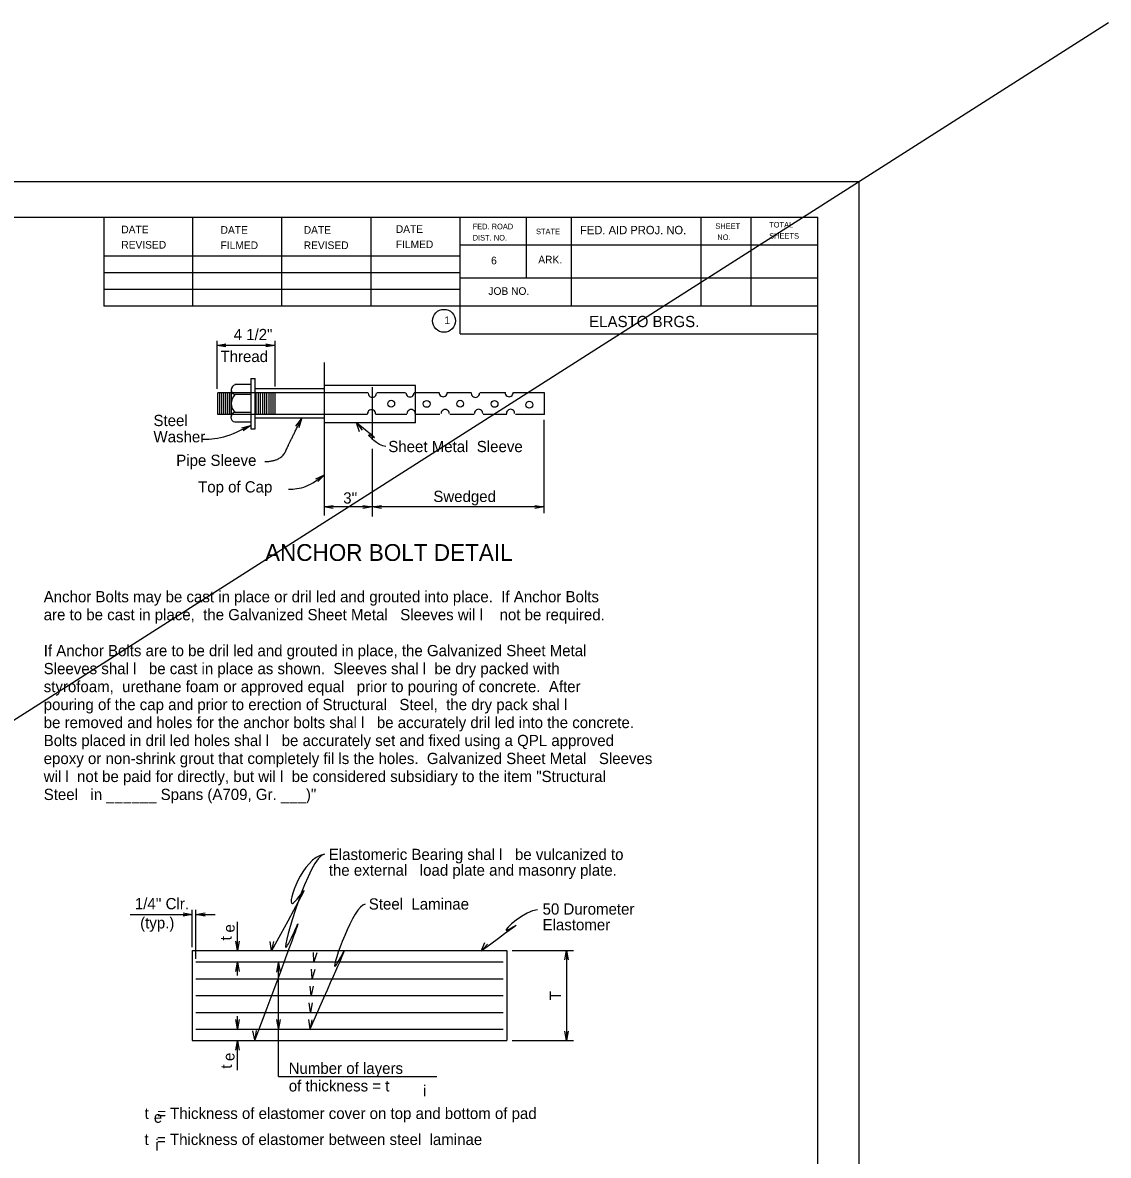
# Model space of a CAD drawing. Extents: x 113 to 232, y -103 to -27.
# Drawn here: x 192.72 to 200.77, y -74.97 to -66.57 of the extents above; entities that cross this region are included whole.
import ezdxf

# ---------------------------------------------------------------- set-up
doc = ezdxf.new("R2010")
doc.units = 0
for name, color, linetype in [('1', 7, 'Continuous'), ('B_Border', 7, 'Continuous'), ('B_Dimension', 7, 'Continuous'), ('B_No_Plot', 7, 'Continuous')]:
    doc.layers.add(name, color=color, linetype=linetype)

msp = doc.modelspace()

# ---------------------------------------------------------------- linework, layer by layer
at = {"layer": '1'}
for p, q in [((174.5006, -83.3011), (200.7719, -66.569)), ((194.1573, -68.9289), (194.1573, -69.2841)), ((194.589, -68.9629), (194.1573, -68.9629)), ((194.589, -68.9289), (194.589, -69.1692)), ((194.9551, -69.091), (194.9551, -70.224)), ((194.4108, -69.2081), (194.4108, -69.5831)), ((194.4108, -69.2081), (194.4421, -69.2081)), ((194.4421, -69.5831), (194.4421, -69.2081)), ((194.589, -69.1569), (194.589, -69.2681)), ((194.2581, -69.3147), (194.1646, -69.3147)), ((194.1646, -69.4745), (194.1646, -69.3147)), ((194.1796, -69.4745), (194.1796, -69.3147)), ((194.1946, -69.4745), (194.1946, -69.3147)), ((194.2096, -69.4745), (194.2096, -69.3147)), ((194.2246, -69.4745), (194.2246, -69.3147)), ((194.2396, -69.4745), (194.2396, -69.3147)), ((194.2553, -69.4745), (194.2553, -69.3147)), ((194.2637, -69.2843), (194.2637, -69.4899)), ((195.2811, -69.3147), (194.2637, -69.3147)), ((194.4108, -69.2524), (194.2912, -69.2524)), ((194.9551, -69.285), (194.4421, -69.285)), ((194.4506, -69.4745), (194.4506, -69.3147)), ((194.4664, -69.4745), (194.4664, -69.3147)), ((194.4822, -69.4745), (194.4822, -69.3147)), ((194.4981, -69.4745), (194.4981, -69.3147)), ((194.5138, -69.4745), (194.5138, -69.3147)), ((194.5296, -69.4745), (194.5296, -69.3147)), ((194.5455, -69.4745), (194.5455, -69.3147)), ((194.5612, -69.4745), (194.5612, -69.3147)), ((194.5752, -69.4717), (194.5752, -69.3147)), ((194.5913, -69.4745), (194.5913, -69.3147)), ((195.6317, -69.2602), (194.9571, -69.2602)), ((195.3103, -69.2722), (195.3103, -69.6644)), ((195.5582, -69.3147), (195.3451, -69.3147)), ((195.6312, -69.3147), (195.6209, -69.3147)), ((195.8046, -69.3147), (195.6312, -69.3147)), ((195.6317, -69.5363), (195.6317, -69.2602)), ((196.0476, -69.3147), (195.8655, -69.3147)), ((196.2992, -69.3147), (196.1099, -69.3147)), ((196.5875, -69.3147), (196.3581, -69.3147)), ((196.5875, -69.4745), (196.5875, -69.3147)), ((194.4108, -69.3282), (194.2923, -69.3282)), ((194.2601, -69.4745), (194.1646, -69.4745)), ((195.2755, -69.4745), (194.2637, -69.4745)), ((194.4108, -69.4597), (194.2922, -69.4597)), ((195.5676, -69.4745), (195.3359, -69.4745)), ((195.6333, -69.4745), (195.6301, -69.4745)), ((195.812, -69.4745), (195.6333, -69.4745)), ((196.0676, -69.4745), (195.8856, -69.4745)), ((196.3103, -69.4745), (196.1338, -69.4745)), ((196.5875, -69.4745), (196.3746, -69.4745)), ((194.4108, -69.5314), (194.2931, -69.5314)), ((194.9551, -69.5033), (194.4421, -69.5033)), ((195.6317, -69.5363), (194.9531, -69.5363)), ((196.5841, -69.5156), (196.5841, -70.2075)), ((194.4108, -69.5831), (194.4421, -69.5831)), ((195.3103, -69.7295), (195.3103, -70.2322)), ((195.3103, -70.1617), (194.9526, -70.1617)), ((196.5841, -70.1617), (195.3103, -70.1617)), ((193.9757, -73.4271), (193.9757, -73.1509)), ((194.0017, -73.5127), (194.0017, -73.1509)), ((193.5154, -73.1837), (193.9757, -73.1837)), ((194.0017, -73.1837), (194.1448, -73.1837)), ((194.3108, -73.4517), (194.3108, -73.2399)), ((193.9757, -73.4527), (196.309, -73.4527)), ((193.9757, -73.4527), (193.9757, -74.1194)), ((196.309, -73.4527), (196.309, -74.1194)), ((196.3493, -73.4527), (196.8044, -73.4527)), ((196.7524, -73.4527), (196.7524, -74.1187)), ((194.0017, -73.5361), (196.283, -73.5361)), ((194.3108, -73.6361), (194.3108, -73.5383)), ((194.616, -74.3853), (194.616, -73.5427)), ((194.0017, -73.6611), (196.283, -73.6611)), ((194.0017, -73.7861), (196.283, -73.7861)), ((194.0017, -73.9111), (196.283, -73.9111)), ((194.3108, -74.0323), (194.3108, -73.938)), ((194.0017, -74.0361), (196.283, -74.0361)), ((193.9757, -74.1194), (196.309, -74.1194)), ((194.3108, -74.3403), (194.3108, -74.1217)), ((196.3493, -74.1187), (196.8044, -74.1187)), ((194.616, -74.3853), (195.7903, -74.3853))]:
    msp.add_line(p, q, dxfattribs=at)
for centre in [(195.4519, -69.3955), (195.7147, -69.3974), (195.963, -69.3955), (196.2185, -69.3974), (196.476, -69.4029)]:
    msp.add_circle(centre, 0.025, dxfattribs=at)
for centre, radius, start, end in [((194.3023, -69.2922), 0.0375, 104.16343, 254.65118), ((195.5907, -69.315), 0.0303, 179.57723, 0.42277), ((195.8371, -69.3131), 0.0303, 179.57723, 0.42277), ((196.326, -69.3131), 0.0303, 179.57723, 0.42277), ((194.3537, -69.3942), 0.0899, 132.97274, 226.91833), ((195.3112, -69.3186), 0.0303, 179.57723, 0.42277), ((196.076, -69.3186), 0.0303, 179.57723, 0.42277), ((194.2979, -69.4956), 0.0362, 99.02769, 259.56758), ((195.3056, -69.4705), 0.0303, 359.57723, 180.42277), ((195.5997, -69.4688), 0.0303, 359.57723, 180.42277), ((195.8517, -69.4688), 0.0303, 359.57723, 180.42277), ((196.0998, -69.4669), 0.0303, 359.57723, 180.42277), ((196.337, -69.4669), 0.0303, 359.57723, 180.42277)]:
    msp.add_arc(centre, radius, start, end, dxfattribs=at)
for points, degree in [([(194.0526, -69.6587), (194.0636, -69.6591), (194.1878, -69.6603), (194.3044, -69.6067), (194.4108, -69.5578)], 3), ([(194.5147, -69.8244), (194.6342, -69.8244), (194.7043, -69.6678), (194.7866, -69.5071)], 2), ([(195.4113, -69.7124), (195.3514, -69.7107), (195.1938, -69.5376), (195.4113, -69.7124), (195.1938, -69.5376)], 3), ([(194.6895, -70.0301), (194.7087, -70.0298), (194.8063, -70.0284), (194.8892, -69.9712), (194.9555, -69.924)], 3), ([(194.9559, -72.738), (194.8442, -72.7509), (194.44, -74.1144), (194.9559, -72.738), (194.44, -74.1144)], 3), ([(194.9559, -72.738), (194.788, -72.7657), (194.5644, -73.4539), (194.9559, -72.738), (194.5644, -73.4539)], 3), ([(195.2579, -73.1091), (195.174, -73.1121), (194.8503, -74.0296), (195.2579, -73.1091), (194.8503, -74.0296)], 3), ([(196.5374, -73.1499), (196.4475, -73.1499), (196.1179, -73.4558), (196.5374, -73.1499), (196.1179, -73.4558)], 3)]:
    msp.add_open_spline(points, degree=degree, dxfattribs=at)
at = {"layer": 'B_Border'}
for p, q in [((177.539, -68.0117), (198.6157, -68.0117)), ((193.319, -68.0117), (193.319, -68.6717)), ((193.979, -68.6717), (193.979, -68.0117)), ((194.639, -68.6717), (194.639, -68.0117)), ((195.3024, -68.6717), (195.3024, -68.0117)), ((195.9624, -68.8784), (195.9624, -68.0117)), ((196.4557, -68.465), (196.4557, -68.0117)), ((196.789, -68.6717), (196.789, -68.0117)), ((197.749, -68.0117), (197.749, -68.6717)), ((198.119, -68.0117), (198.119, -68.6717)), ((198.6157, -81.7084), (198.6157, -68.0117)), ((198.6157, -68.2184), (195.9624, -68.2184)), ((195.959, -68.3017), (193.319, -68.3017)), ((195.9624, -68.425), (193.319, -68.425)), ((198.6157, -68.465), (195.9624, -68.465)), ((195.9624, -68.5484), (193.319, -68.5484)), ((198.6157, -68.6717), (193.319, -68.6717)), ((195.9624, -68.8784), (198.6157, -68.8784))]:
    msp.add_line(p, q, dxfattribs=at)
msp.add_circle((195.8431, -68.7807), 0.085, dxfattribs=at)
at = {"layer": 'B_Dimension'}
for points in [[(194.2256, -68.9749), (194.1573, -68.9629), (194.2256, -68.9509)], [(194.5206, -68.9509), (194.589, -68.9629), (194.5206, -68.9749)], [(194.3437, -69.5754), (194.4108, -69.5578), (194.3537, -69.5972)], [(194.7448, -69.5625), (194.7866, -69.5071), (194.7662, -69.5734)], [(195.2152, -69.6036), (195.1938, -69.5376), (195.2365, -69.5923)], [(194.8928, -69.9538), (194.9555, -69.924), (194.9068, -69.9734)], [(195.0209, -70.1738), (194.9526, -70.1617), (195.0209, -70.1497)], [(195.242, -70.1497), (195.3103, -70.1617), (195.242, -70.1738)], [(195.3786, -70.1738), (195.3103, -70.1617), (195.3786, -70.1497)], [(196.5158, -70.1497), (196.5841, -70.1617), (196.5158, -70.1738)], [(193.9074, -73.1717), (193.9757, -73.1837), (193.9074, -73.1958)], [(194.07, -73.1958), (194.0017, -73.1837), (194.07, -73.1717)], [(194.3229, -73.3834), (194.3108, -73.4517), (194.2988, -73.3834)], [(194.5783, -73.3859), (194.5644, -73.4539), (194.5542, -73.3853)], [(196.165, -73.4049), (196.1179, -73.4558), (196.1448, -73.3918)], [(194.8998, -73.4692), (194.8784, -73.5352), (194.8759, -73.4659)], [(196.7404, -73.5211), (196.7524, -73.4527), (196.7645, -73.5211)], [(194.2988, -73.6066), (194.3108, -73.5383), (194.3229, -73.6066)], [(194.604, -73.6111), (194.616, -73.5427), (194.6281, -73.6111)], [(194.8845, -73.5924), (194.8645, -73.6588), (194.8606, -73.5895)], [(194.8734, -73.7168), (194.857, -73.7843), (194.8493, -73.7153)], [(194.866, -73.8409), (194.8527, -73.909), (194.842, -73.8405)], [(194.3229, -73.964), (194.3108, -74.0323), (194.2988, -73.964)], [(194.6277, -73.9622), (194.6156, -74.0305), (194.6036, -73.9622)], [(194.8631, -73.9648), (194.8498, -74.0329), (194.8391, -73.9644)], [(194.4498, -74.0457), (194.44, -74.1144), (194.4257, -74.0465)], [(196.7645, -74.0504), (196.7524, -74.1187), (196.7404, -74.0504)], [(194.2988, -74.1901), (194.3108, -74.1217), (194.3229, -74.1901)]]:
    msp.add_lwpolyline(points, dxfattribs=at)
at = {"layer": 'B_No_Plot'}
msp.add_lwpolyline([(176.5874, -67.748), (198.9207, -67.748), (198.9207, -81.972), (176.5874, -81.972)], close=True, dxfattribs=at)

# ---------------------------------------------------------------- texts
at = {"layer": '1'}
for s, height, p in [('ELASTO BRGS.', 0.083334, (196.92, -68.8275)), ('4 1/2"', 0.08333, (194.2827, -68.924)), ('Thread', 0.08325, (194.185, -69.0866)), ('Steel', 0.08333, (193.6878, -69.5615)), ('Washer', 0.08333, (193.6878, -69.6823)), ('Sheet Metal  Sleeve', 0.083334, (195.4298, -69.7547)), ('Pipe Sleeve', 0.083334, (193.8567, -69.8569)), ('Top of Cap', 0.08325, (194.0187, -70.0541)), ("3''", 0.08325, (195.0954, -70.1364)), ('Swedged', 0.08325, (195.7639, -70.1247)), ('ANCHOR BOLT DETAIL', 0.12487, (194.5149, -70.5618)), ('Anchor Bolts may be cast in place or dril led and grouted into place.  If Anchor Bolts ', 0.083334, (192.8733, -70.8686)), ('are to be cast in place,  the Galvanized Sheet Metal   Sleeves wil l    not be required.', 0.083334, (192.8733, -71.0019)), ('If Anchor Bolts are to be dril led and grouted in place, the Galvanized Sheet Metal   ', 0.083334, (192.8733, -71.2686)), ('Sleeves shal l   be cast in place as shown.  Sleeves shal l  be dry packed with ', 0.083334, (192.8733, -71.4019)), ('styrofoam,  urethane foam or approved equal   prior to pouring of concrete.  After ', 0.083334, (192.8733, -71.5353)), ('pouring of the cap and prior to erection of Structural   Steel,  the dry pack shal l  ', 0.083334, (192.8733, -71.6686)), ('be removed and holes for the anchor bolts shal l   be accurately dril led into the concrete. ', 0.083334, (192.8733, -71.8019)), ('Bolts placed in dril led holes shal l   be accurately set and fixed using a QPL approved', 0.083334, (192.8733, -71.9353)), ('epoxy or non-shrink grout that completely fil ls the holes.  Galvanized Sheet Metal   Sleeves ', 0.083334, (192.8733, -72.0686)), ('wil l  not be paid for directly, but wil l  be considered subsidiary to the item "Structural ', 0.083334, (192.8733, -72.2019)), ('Steel   in ______ Spans (A709, Gr. ___)"', 0.083334, (192.8733, -72.3353)), ('Elastomeric Bearing shal l   be vulcanized to ', 0.083334, (194.9883, -72.7805)), ('the external   load plate and masonry plate.', 0.083334, (194.9883, -72.8971)), ("1/4'' Clr.", 0.08333, (193.5493, -73.1457)), ('Steel  Laminae', 0.083334, (195.2852, -73.148)), ('50 Durometer', 0.083334, (196.5745, -73.1854)), ('(typ.)', 0.08333, (193.5888, -73.2879)), ('Elastomer', 0.08333, (196.5745, -73.3021)), ('Number of layers', 0.083334, (194.6905, -74.3665)), ('of thickness = t', 0.083334, (194.6917, -74.4972)), ('i', 0.0833, (195.6876, -74.5335)), ('t  = Thickness of elastomer cover on top and bottom of pad', 0.083334, (193.6224, -74.7014)), ('e', 0.0833, (193.6903, -74.7296)), ('t  = Thickness of elastomer between steel  laminae', 0.083334, (193.621, -74.8946)), ('i', 0.0833, (193.7004, -74.9354))]:
    msp.add_text(s, height=height, dxfattribs=at).set_placement(p)
for s, p in [('e', (194.2896, -73.3182)), ('t', (194.2673, -73.3767)), ('T', (196.7108, -73.821)), ('e', (194.2884, -74.2714)), ('t', (194.2692, -74.3283))]:
    msp.add_text(s, height=0.0833, rotation=90, dxfattribs=at).set_placement(p)
at = {"layer": 'B_Border'}
for s, height, p in [('SHEET', 0.04132, (197.8557, -68.0984)), ('TOTAL', 0.04132, (198.2557, -68.0884)), ('DATE', 0.05666, (193.449, -68.1317)), ('DATE', 0.05666, (194.1857, -68.135)), ('DATE', 0.05666, (194.8024, -68.135)), ('DATE', 0.05666, (195.4857, -68.1284)), ('FED. ROAD', 0.04132, (196.0557, -68.1017)), ('STATE', 0.04132, (196.5257, -68.1384)), ('FED. AID PROJ. NO.', 0.062, (196.8524, -68.1384)), (' NO.', 0.04132, (197.8557, -68.1817)), ('SHEETS', 0.04132, (198.2557, -68.1717)), ('REVISED', 0.05666, (193.449, -68.245)), ('FILMED', 0.05666, (194.1857, -68.2484)), ('REVISED', 0.05666, (194.8024, -68.2484)), ('FILMED', 0.05666, (195.4857, -68.2417)), ('DIST. NO.', 0.04132, (196.0557, -68.185)), ('6', 0.0567, (196.1924, -68.3617)), ('ARK.', 0.05666, (196.5424, -68.355)), ('JOB NO.', 0.05666, (196.1724, -68.5884)), ('1', 0.0567, (195.8457, -68.805))]:
    msp.add_text(s, height=height, dxfattribs=at).set_placement(p)

doc.saveas('drawing.dxf')
